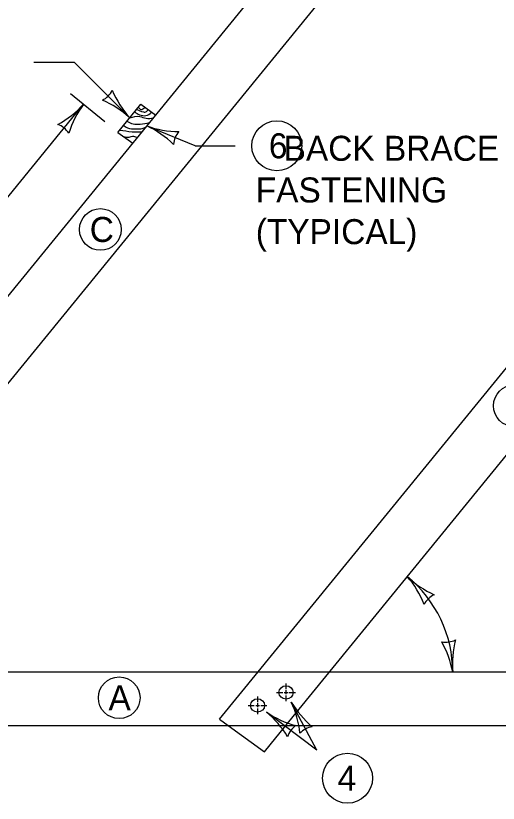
# Model space of a CAD drawing. Extents: x 49991.4 to 50021, y 49987.6 to 50011.4.
# Drawn here: x 50011.907 to 50013.065, y 49993.161 to 49995.05 of the extents above; entities that cross this region are included whole.
import ezdxf

# ---------------------------------------------------------------- set-up
doc = ezdxf.new("R2010")
doc.units = 0
for name, color, linetype in [('Level 1', 7, 'Continuous'), ('Level 2', 7, 'Continuous'), ('Level 3', 7, 'Continuous'), ('Level 4', 7, 'Continuous'), ('Level 5', 7, 'Continuous')]:
    doc.layers.add(name, color=color, linetype=linetype)

msp = doc.modelspace()

# ---------------------------------------------------------------- linework, layer by layer
at = {"layer": 'Level 1'}
for p, q in [((50011.1535, 49993.4768), (50013.1083, 49995.8723)), ((50011.2191, 49993.3474), (50013.1526, 49995.7167)), ((50012.1521, 49994.7706), (50012.2072, 49994.8381)), ((50012.2072, 49994.8381), (50012.2432, 49994.8122)), ((50012.1521, 49994.7706), (50012.1881, 49994.7446)), ((50012.3964, 49993.3626), (50013.4541, 49994.6588)), ((50012.5552, 49993.3474), (50013.4984, 49994.5032)), ((50013.6869, 49993.4751), (50010.8912, 49993.4751)), ((50012.3964, 49993.3626), (50012.4173, 49993.3474)), ((50010.8912, 49993.3474), (50013.6869, 49993.3474))]:
    msp.add_line(p, q, dxfattribs=at)
for centre in [(50012.5559, 49993.4269), (50012.4876, 49993.3957)]:
    msp.add_ellipse(centre, major_axis=(0.017, 0), ratio=0.940299, dxfattribs=at)
for points in [[(50012.2013, 49994.8312), (50012.2078, 49994.8256), (50012.2176, 49994.8306)], [(50012.1811, 49994.8057), (50012.205, 49994.8088), (50012.2204, 49994.8043), (50012.2379, 49994.8057)], [(50012.1932, 49994.8195), (50012.2045, 49994.8129), (50012.2198, 49994.8108), (50012.2327, 49994.8181), (50012.2337, 49994.819)], [(50012.198, 49994.8256), (50012.2137, 49994.8195), (50012.2209, 49994.8205), (50012.2257, 49994.8245), (50012.2265, 49994.8242)], [(50012.1753, 49994.7965), (50012.1888, 49994.791), (50012.2061, 49994.7905), (50012.2283, 49994.7939)], [(50012.1567, 49994.7762), (50012.1866, 49994.7722), (50012.2007, 49994.7716), (50012.21, 49994.7716)], [(50012.1649, 49994.7879), (50012.1753, 49994.7818), (50012.1963, 49994.7788), (50012.2111, 49994.7797), (50012.2196, 49994.7832)], [(50012.1671, 49994.7605), (50012.1796, 49994.7593), (50012.1898, 49994.7614), (50012.1996, 49994.7579)]]:
    msp.add_spline(points, degree=3, dxfattribs=at)
at = {"layer": 'Level 2'}
for centre, radius in [((50012.5338, 49994.7385), 0.06), ((50012.1105, 49994.5376), 0.05), ((50013.1037, 49994.1146), 0.05), ((50012.1556, 49993.414), 0.05), ((50012.7035, 49993.221), 0.06)]:
    msp.add_circle(centre, radius, dxfattribs=at)
at = {"layer": 'Level 3'}
for p, q in [((50012.0486, 49994.9386), (50011.9511, 49994.9386)), ((50012.1808, 49994.8057), (50012.0486, 49994.9386)), ((50012.1211, 49994.7959), (50012.0387, 49994.8632)), ((50010.9407, 49993.4547), (50012.0697, 49994.8379)), ((50012.3379, 49994.7385), (50012.2362, 49994.7802)), ((50012.3379, 49994.7385), (50012.4338, 49994.7385)), ((50012.6299, 49993.2884), (50012.5683, 49993.4038)), ((50012.6299, 49993.2884), (50012.5088, 49993.3797))]:
    msp.add_line(p, q, dxfattribs=at)
for centre, radius, start, end in [((50012.0904, 49994.8966), 0.0548, 296.995, 332.7173), ((50012.3447, 49994.9559), 0.2223, 202.3122, 222.4957), ((50012.0239, 49994.6335), 0.233, 47.6835, 66.9333), ((50011.9034, 49994.9854), 0.2223, 298.2339, 318.4174), ((50012.2572, 49994.6996), 0.233, 143.6052, 162.855), ((50011.9886, 49994.7386), 0.0548, 32.9167, 68.6391), ((50012.1292, 49994.584), 0.2223, 45.1609, 65.3444), ((50012.2996, 49995.0057), 0.233, 250.5322, 269.7821), ((50012.3405, 49994.7374), 0.0548, 139.8437, 175.5661), ((50012.6594, 49993.4751), 0.2966, 0, 50.782), ((50012.6794, 49993.5587), 0.2223, 20.9109, 41.0944), ((50013.0079, 49993.8733), 0.233, 226.2822, 245.532), ((50012.9351, 49993.6118), 0.0548, 115.5937, 151.316), ((50012.9396, 49993.6023), 0.0548, 259.4732, 295.1956), ((50012.7266, 49993.434), 0.233, 10.1617, 29.4115), ((50013.1774, 49993.4944), 0.2223, 164.7904, 184.9739), ((50012.368, 49993.3073), 0.2223, 5.5491, 25.7326), ((50012.7682, 49993.5235), 0.233, 210.9204, 230.1703), ((50012.3678, 49993.2078), 0.2223, 30.4426, 50.6261), ((50012.6397, 49993.5724), 0.233, 235.8139, 255.0637), ((50012.6112, 49993.3025), 0.0548, 125.1254, 160.8477), ((50012.6287, 49993.2907), 0.0548, 100.2319, 135.9543)]:
    msp.add_arc(centre, radius, start, end, dxfattribs=at)
at = {"layer": 'Level 4'}
for p, q in [((50012.4173, 49993.3474), (50012.5042, 49993.2847)), ((50012.5042, 49993.2847), (50012.5552, 49993.3474))]:
    msp.add_line(p, q, dxfattribs=at)
at = {"layer": 'Level 5'}
for p, q in [((50012.5558, 49993.4481), (50012.5558, 49993.4343)), ((50012.5558, 49993.432), (50012.5558, 49993.4228)), ((50012.4875, 49993.4169), (50012.4875, 49993.4031)), ((50012.5332, 49993.4269), (50012.5479, 49993.4269)), ((50012.5515, 49993.4269), (50012.5609, 49993.4269)), ((50012.5558, 49993.4194), (50012.5558, 49993.4056)), ((50012.5638, 49993.4269), (50012.5785, 49993.4269)), ((50012.4649, 49993.3957), (50012.4796, 49993.3957)), ((50012.4832, 49993.3957), (50012.4926, 49993.3957)), ((50012.4875, 49993.4008), (50012.4875, 49993.3916)), ((50012.4955, 49993.3957), (50012.5102, 49993.3957)), ((50012.4875, 49993.3882), (50012.4875, 49993.3744))]:
    msp.add_line(p, q, dxfattribs=at)

# ---------------------------------------------------------------- texts
at = {"layer": 'Level 2'}
for s, p in [('6', (50012.5147, 49994.7084)), ('   BACK BRACE', (50012.4833, 49994.7024)), ('FASTENING', (50012.4833, 49994.6024)), ('C', (50012.0849, 49994.5076)), ('(TYPICAL)', (50012.4833, 49994.5024)), ('A', (50012.1299, 49993.384)), ('4', (50012.6796, 49993.191))]:
    msp.add_text(s, height=0.06, dxfattribs=at).set_placement(p)

doc.saveas('drawing.dxf')
